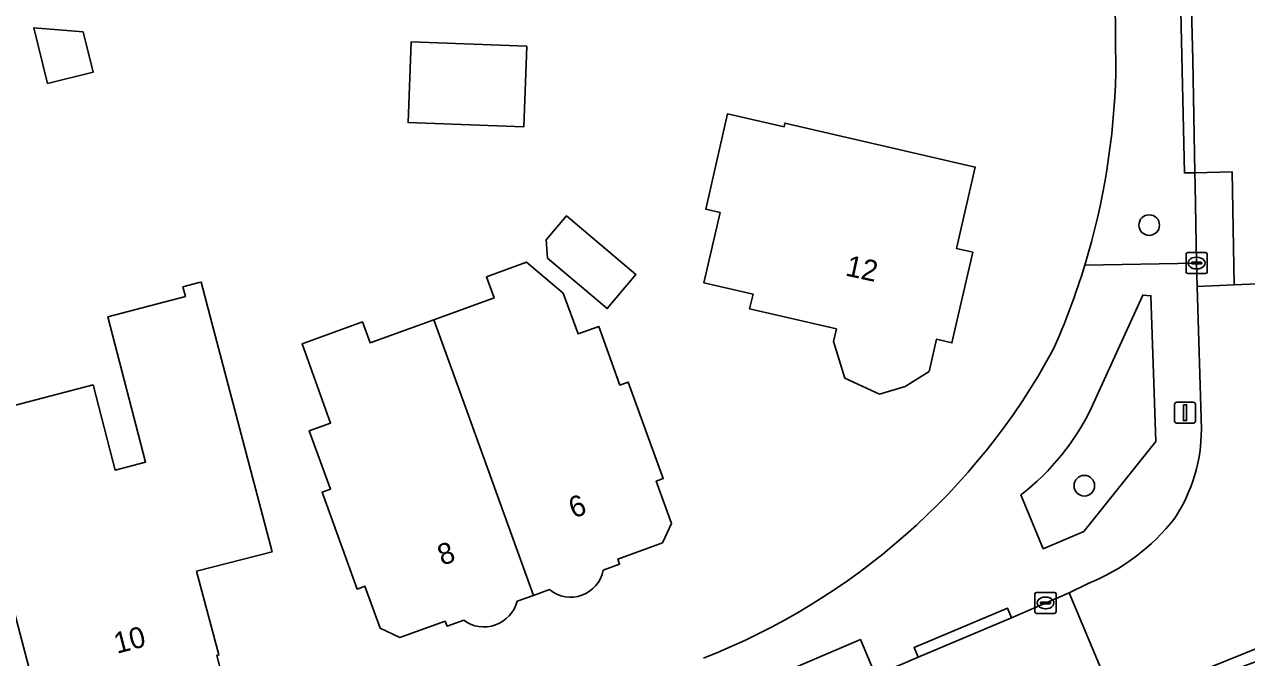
# Model space of a CAD drawing. Extents: x 161772 to 163126, y 383092 to 383917.
# Drawn here: x 162222.7 to 162280.8, y 383514.6 to 383544.7 of the extents above; entities that cross this region are included whole.
import ezdxf

# ---------------------------------------------------------------- set-up
doc = ezdxf.new("R2010")
doc.units = 0
for name, color, linetype in [('IMGEO_Boom', 7, 'Continuous'), ('IMGEO_Erf', 7, 'Continuous'), ('IMGEO_Groenvoorziening', 7, 'Continuous'), ('IMGEO_Kolk', 7, 'Continuous'), ('IMGEO_Lichtmast', 7, 'Continuous'), ('IMGEO_Pand', 7, 'Continuous'), ('IMGEO_Pand_nummerreeks', 7, 'Continuous'), ('IMGEO_Parkeervlak_open', 7, 'Continuous'), ('IMGEO_Rijbaan_lokaal_gesloten', 7, 'Continuous'), ('IMGEO_Rijbaan_lokaal_open', 7, 'Continuous'), ('IMGEO_Voetpad_gesloten', 7, 'Continuous'), ('IMGEO_Voetpad_open', 7, 'Continuous')]:
    doc.layers.add(name, color=color, linetype=linetype)

msp = doc.modelspace()

# ---------------------------------------------------------------- linework, layer by layer
at = {"layer": 'IMGEO_Boom'}
for centre in [(162276.194, 383535.151), (162273.111, 383522.755)]:
    msp.add_circle(centre, 0.489, dxfattribs=at)
at = {"layer": 'IMGEO_Erf'}
for points in [[(162274.609, 383542.395), (162274.444, 383559.797)], [(162243.597, 383516.356), (162242.809, 383516.07), (162242.72, 383516.314), (162240.566, 383515.536), (162239.621, 383515.979), (162238.9, 383517.975), (162238.533, 383517.842), (162236.868, 383522.449), (162237.26, 383522.591), (162236.256, 383525.371), (162237.271, 383525.737), (162235.911, 383529.502), (162238.792, 383530.543), (162239.149, 383529.555), (162242.185, 383530.652), (162245.042, 383531.684), (162244.678, 383532.692), (162246.59, 383533.384)], [(162246.59, 383533.384), (162248.335, 383531.912), (162249.034, 383529.977), (162250.017, 383530.332), (162251.025, 383527.543), (162251.426, 383527.688), (162253.084, 383523.098), (162252.751, 383522.977), (162253.481, 383520.957), (162253.049, 383520.038), (162250.922, 383519.269), (162251.012, 383519.019), (162250.231, 383518.737)], [(162247.685, 383517.82), (162246.912, 383517.541), (162246.142, 383517.263)]]:
    msp.add_lwpolyline(points, dxfattribs=at)
for points in [[(162223.812, 383541.883), (162223.151, 383544.53), (162225.5, 383544.334), (162225.977, 383542.423)], [(162246.598, 383543.656), (162246.456, 383539.819), (162240.956, 383540.022), (162241.098, 383543.859)], [(162255.788, 383535.749), (162255.104, 383535.907), (162256.15, 383540.446), (162258.83, 383539.829), (162258.869, 383539.999), (162263.049, 383539.035), (162267.921, 383537.912), (162267.028, 383534.038), (162267.806, 383533.859), (162266.813, 383529.551), (162266.079, 383529.721), (162265.727, 383528.193), (162264.591, 383527.482), (162263.362, 383527.107), (162261.717, 383527.865), (162261.181, 383529.615), (162261.319, 383530.213), (162257.194, 383531.164), (162257.358, 383531.873), (162255.019, 383532.412)], [(162247.576, 383533.58), (162247.527, 383534.45), (162248.479, 383535.587), (162251.787, 383532.795), (162250.422, 383531.178)], [(162231.022, 383532.419), (162231.115, 383532.443), (162231.625, 383530.499), (162234.483, 383519.611), (162230.896, 383518.695), (162231.959, 383514.707), (162231.853, 383514.679), (162232.162, 383513.494), (162231.579, 383513.336), (162231.816, 383512.378), (162228.506, 383511.506), (162228.256, 383512.479), (162224.639, 383511.519), (162223.972, 383514.088), (162222.998, 383513.832), (162221.834, 383518.302), (162219.838, 383525.954), (162225.972, 383527.553), (162227.031, 383523.493), (162228.474, 383523.869), (162226.67, 383530.788), (162230.368, 383531.753), (162230.247, 383532.217)]]:
    msp.add_lwpolyline(points, close=True, dxfattribs=at)
for centre, radius, start, end in [((162240.224, 383543.256), 34.395, 343.07499, 358.56529), ((162240.409, 383543.176), 34.195, 335.87658, 343.11386), ((162243.211, 383544.682), 32.352, 291.38148, 331.40902), ((162248.692, 383519.017), 1.564, 229.91075, 349.70454), ((162244.56, 383517.677), 1.635, 233.90731, 345.32331)]:
    msp.add_arc(centre, radius, start, end, dxfattribs=at)
at = {"layer": 'IMGEO_Groenvoorziening'}
for points in [[(162276.505, 383524.852), (162276.276, 383531.794), (162275.891, 383531.818), (162273.473, 383526.507)], [(162270.086, 383522.316), (162271.153, 383519.757), (162273.085, 383520.577), (162276.505, 383524.852)]]:
    msp.add_lwpolyline(points, dxfattribs=at)
msp.add_lwpolyline([(162258.144, 383511.658), (162263.172, 383513.747), (162262.46, 383515.448), (162257.425, 383513.279)], close=True, dxfattribs=at)
msp.add_arc((162263.026, 383531.485), 11.572, 307.5929, 334.51957, dxfattribs=at)
at = {"layer": 'IMGEO_Kolk'}
for p, q in [((162278.024, 383533.844), (162278.876, 383533.844)), ((162277.949, 383532.918), (162277.949, 383533.77)), ((162278.208, 383533.338), (162278.208, 383533.35)), ((162278.646, 383533.301), (162278.248, 383533.301)), ((162278.251, 383533.387), (162278.649, 383533.387)), ((162278.437, 383533.624), (162278.462, 383533.624)), ((162278.692, 383533.35), (162278.692, 383533.338)), ((162278.95, 383533.77), (162278.95, 383532.918)), ((162278.876, 383532.844), (162278.024, 383532.844)), ((162278.46, 383533.064), (162278.435, 383533.064)), ((162270.763, 383516.756), (162270.763, 383517.608)), ((162270.838, 383517.682), (162271.69, 383517.682)), ((162271.764, 383517.608), (162271.764, 383516.756)), ((162271.022, 383517.176), (162271.022, 383517.188)), ((162271.46, 383517.139), (162271.062, 383517.139)), ((162271.065, 383517.225), (162271.463, 383517.225)), ((162271.251, 383517.462), (162271.276, 383517.462)), ((162271.506, 383517.188), (162271.506, 383517.176)), ((162271.69, 383516.682), (162270.838, 383516.682)), ((162271.274, 383516.902), (162271.249, 383516.902))]:
    msp.add_line(p, q, dxfattribs=at)
for points in [[(162278.024, 383533.844), (162278.876, 383533.844)], [(162277.949, 383532.918), (162277.949, 383533.77)], [(162278.95, 383533.77), (162278.95, 383532.918)], [(162278.876, 383532.844), (162278.024, 383532.844)], [(162270.763, 383516.756), (162270.763, 383517.608)], [(162270.838, 383517.682), (162271.69, 383517.682)], [(162271.764, 383517.608), (162271.764, 383516.756)], [(162271.69, 383516.682), (162270.838, 383516.682)]]:
    msp.add_lwpolyline(points, dxfattribs=at)
for centre, radius, start, end in [((162278.026, 383533.768), 0.0765, 91.55205, 178.44795), ((162278.026, 383533.768), 0.0765, 91.55205, 178.44795), ((162278.874, 383533.768), 0.0765, 1.55205, 88.44795), ((162278.874, 383533.768), 0.0765, 1.55205, 88.44795), ((162278.248, 383533.347), 0.0403, 85.87752, 175.75265), ((162278.245, 383533.337), 0.0366, 178.93798, 274.71019), ((162278.649, 383533.344), 0.043, 264.86636, 352.45326), ((162278.653, 383533.349), 0.0386, 1.73085, 96.63898), ((162278.026, 383532.92), 0.0765, 181.55205, 268.44795), ((162278.026, 383532.92), 0.0765, 181.55205, 268.44795), ((162278.874, 383532.92), 0.0765, 271.55205, 358.44795), ((162278.874, 383532.92), 0.0765, 271.55205, 358.44795), ((162270.84, 383517.606), 0.0765, 91.55205, 178.44795), ((162270.84, 383517.606), 0.0765, 91.55205, 178.44795), ((162271.688, 383517.606), 0.0765, 1.55205, 88.44795), ((162271.688, 383517.606), 0.0765, 1.55205, 88.44795), ((162271.062, 383517.185), 0.0403, 85.87752, 175.75265), ((162271.059, 383517.175), 0.0366, 178.93798, 274.71019), ((162271.463, 383517.182), 0.043, 264.86636, 352.45326), ((162271.467, 383517.187), 0.0386, 1.73085, 96.63898), ((162270.84, 383516.758), 0.0765, 181.55205, 268.44795), ((162270.84, 383516.758), 0.0765, 181.55205, 268.44795), ((162271.688, 383516.758), 0.0765, 271.55205, 358.44795), ((162271.688, 383516.758), 0.0765, 271.55205, 358.44795)]:
    msp.add_arc(centre, radius, start, end, dxfattribs=at)
for centre, major_axis, ratio, start_param, end_param in [((162278.436, 383533.344), (-0.387, 0.002), 0.722429, 4.712389, 7.853982), ((162278.461, 383533.344), (-0.39, 0.002), 0.717154, 1.570796, 4.712389), ((162271.25, 383517.182), (-0.387, 0.002), 0.722429, 4.712389, 7.853982), ((162271.275, 383517.182), (-0.39, 0.002), 0.717154, 1.570796, 4.712389)]:
    msp.add_ellipse(centre, major_axis=major_axis, ratio=ratio, start_param=start_param, end_param=end_param, dxfattribs=at)
at = {"layer": 'IMGEO_Lichtmast'}
for p, q in [((162277.402, 383525.829), (162277.402, 383526.629)), ((162277.402, 383526.629), (162277.402, 383525.829)), ((162277.502, 383526.729), (162278.292, 383526.729)), ((162278.292, 383526.729), (162277.502, 383526.729)), ((162278.392, 383526.629), (162278.392, 383525.829)), ((162278.392, 383525.829), (162278.392, 383526.629)), ((162278.292, 383525.729), (162277.502, 383525.729)), ((162277.502, 383525.729), (162278.292, 383525.729))]:
    msp.add_line(p, q, dxfattribs=at)
msp.add_lwpolyline([(162277.822, 383526.604), (162277.972, 383526.604), (162277.972, 383525.854), (162277.822, 383525.854), (162277.822, 383526.604)], dxfattribs=at)
for centre, start, end in [((162277.502, 383526.629), 90, 180), ((162277.502, 383526.629), 90, 180), ((162278.292, 383526.629), 0, 90), ((162278.292, 383526.629), 360, 90), ((162277.502, 383525.829), 180, 270), ((162277.502, 383525.829), 180, 270), ((162278.292, 383525.829), 270, 0), ((162278.292, 383525.829), 270, 0)]:
    msp.add_arc(centre, 0.1, start, end, dxfattribs=at)
at = {"layer": 'IMGEO_Pand'}
for points in [[(162223.812, 383541.883), (162225.977, 383542.423), (162225.5, 383544.334), (162223.151, 383544.53)], [(162246.598, 383543.656), (162241.098, 383543.859), (162240.956, 383540.022), (162246.456, 383539.819)], [(162257.358, 383531.873), (162257.194, 383531.164), (162261.319, 383530.213), (162261.181, 383529.615), (162261.717, 383527.865), (162263.362, 383527.107), (162264.591, 383527.482), (162265.727, 383528.193), (162266.079, 383529.721), (162266.813, 383529.551), (162267.806, 383533.859), (162267.028, 383534.038), (162267.921, 383537.912), (162263.049, 383539.035), (162258.869, 383539.999), (162258.83, 383539.829), (162256.15, 383540.446), (162255.104, 383535.907), (162255.788, 383535.749), (162255.019, 383532.412)], [(162248.479, 383535.587), (162247.527, 383534.45), (162247.576, 383533.58), (162250.422, 383531.178), (162251.787, 383532.795)], [(162231.625, 383530.499), (162231.115, 383532.443), (162231.022, 383532.419), (162230.247, 383532.217), (162230.368, 383531.753), (162226.67, 383530.788), (162228.474, 383523.869), (162227.031, 383523.493), (162225.972, 383527.553), (162219.838, 383525.954), (162221.834, 383518.302), (162222.998, 383513.832), (162223.972, 383514.088), (162224.639, 383511.519), (162228.256, 383512.479), (162228.506, 383511.506), (162231.816, 383512.378), (162231.579, 383513.336), (162232.162, 383513.494), (162231.853, 383514.679), (162231.959, 383514.707), (162230.896, 383518.695), (162234.483, 383519.611)]]:
    msp.add_lwpolyline(points, close=True, dxfattribs=at)
for points in [[(162250.231, 383518.737), (162251.012, 383519.019), (162250.922, 383519.269), (162253.049, 383520.038), (162253.481, 383520.957), (162252.751, 383522.977), (162253.084, 383523.098), (162251.426, 383527.688), (162251.025, 383527.543), (162250.017, 383530.332), (162249.034, 383529.977), (162248.335, 383531.912), (162246.59, 383533.384), (162244.678, 383532.692), (162245.042, 383531.684), (162242.185, 383530.652), (162243.54, 383526.893), (162246.912, 383517.541), (162247.685, 383517.82)], [(162246.142, 383517.263), (162246.912, 383517.541), (162243.54, 383526.893), (162242.185, 383530.652), (162239.149, 383529.555), (162238.792, 383530.543), (162235.911, 383529.502), (162237.271, 383525.737), (162236.256, 383525.371), (162237.26, 383522.591), (162236.868, 383522.449), (162238.533, 383517.842), (162238.9, 383517.975), (162239.621, 383515.979), (162240.566, 383515.536), (162242.72, 383516.314), (162242.809, 383516.07), (162243.597, 383516.356)]]:
    msp.add_lwpolyline(points, dxfattribs=at)
for centre, radius, start, end in [((162248.692, 383519.017), 1.564, 229.91075, 349.70454), ((162244.56, 383517.677), 1.635, 233.90731, 345.32331)]:
    msp.add_arc(centre, radius, start, end, dxfattribs=at)
at = {"layer": 'IMGEO_Parkeervlak_open'}
msp.add_lwpolyline([(162280.132, 383537.677), (162278.369, 383537.642), (162278.386, 383537.045), (162278.451, 383533.344), (162278.481, 383532.232), (162280.234, 383532.311)], close=True, dxfattribs=at)
at = {"layer": 'IMGEO_Rijbaan_lokaal_gesloten'}
msp.add_lwpolyline([(162232.719, 383498.477), (162232.788, 383498.498), (162232.857, 383498.517), (162240.887, 383500.821), (162243.486, 383501.569), (162252.383, 383504.531), (162257.966, 383506.692), (162263.678, 383509.123), (162274.11, 383513.54), (162272.382, 383517.659), (162269.646, 383516.479), (162265.21, 383514.61), (162264.518, 383514.306), (162263.172, 383513.747), (162258.144, 383511.658), (162256.707, 383511.061), (162255.312, 383510.481)], dxfattribs=at)
at = {"layer": 'IMGEO_Rijbaan_lokaal_open'}
for points in [[(162278.129, 383548.282), (162278.172, 383546.716), (162278.208, 383545.419), (162278.262, 383543.027), (162278.369, 383537.642), (162280.132, 383537.677), (162280.234, 383532.311), (162283.53, 383532.459), (162283.187, 383549.72)], [(162285.569, 383530.634), (162285.455, 383532.546), (162283.53, 383532.459), (162280.234, 383532.311), (162278.481, 383532.232), (162278.676, 383525.441)], [(162273.292, 383518.111), (162272.382, 383517.659), (162274.11, 383513.54), (162274.699, 383512.137), (162279.146, 383514.141), (162282.946, 383515.674), (162285.57, 383516.52), (162286.631, 383516.849)]]:
    msp.add_lwpolyline(points, dxfattribs=at)
for centre, radius, start, end in [((162270.945, 383525.442), 7.731, 326.77271, 359.99023), ((162269.534, 383527.403), 10.023, 292.01944, 321.80931)]:
    msp.add_arc(centre, radius, start, end, dxfattribs=at)
at = {"layer": 'IMGEO_Voetpad_gesloten'}
for points in [[(162278.481, 383532.232), (162278.451, 383533.344), (162273.13, 383533.243)], [(162278.676, 383525.441), (162278.481, 383532.232)], [(162275.891, 383531.818), (162276.276, 383531.794), (162276.505, 383524.852), (162273.085, 383520.577), (162271.153, 383519.757), (162270.086, 383522.316)], [(162273.473, 383526.507), (162275.891, 383531.818)], [(162256.015, 383512.721), (162256.707, 383511.061), (162258.144, 383511.658), (162257.425, 383513.279), (162262.46, 383515.448), (162263.172, 383513.747), (162264.518, 383514.306), (162265.21, 383514.61), (162265.016, 383515.069), (162269.452, 383516.939), (162269.646, 383516.479), (162272.382, 383517.659), (162273.292, 383518.111)]]:
    msp.add_lwpolyline(points, dxfattribs=at)
for centre, radius, start, end in [((162240.409, 383543.176), 34.195, 335.87658, 343.11386), ((162243.211, 383544.682), 32.352, 291.38148, 331.40902), ((162263.026, 383531.485), 11.572, 307.5929, 334.51957), ((162270.945, 383525.442), 7.731, 326.77271, 359.99023), ((162269.534, 383527.403), 10.023, 292.01944, 321.80931)]:
    msp.add_arc(centre, radius, start, end, dxfattribs=at)
at = {"layer": 'IMGEO_Voetpad_open'}
for points in [[(162273.743, 383601.16), (162274.444, 383559.797), (162274.609, 383542.395)], [(162273.13, 383533.243), (162278.451, 383533.344), (162278.386, 383537.045), (162278.369, 383537.642), (162277.87, 383537.632), (162277.674, 383546.706), (162278.172, 383546.716), (162278.129, 383548.282)]]:
    msp.add_lwpolyline(points, dxfattribs=at)
for points in [[(162278.369, 383537.642), (162278.262, 383543.027), (162278.208, 383545.419), (162278.172, 383546.716), (162277.674, 383546.706), (162277.87, 383537.632)], [(162265.21, 383514.61), (162269.646, 383516.479), (162269.452, 383516.939), (162265.016, 383515.069)], [(162279.146, 383514.141), (162279.319, 383513.673), (162285.743, 383516.052), (162285.57, 383516.52), (162282.946, 383515.674)]]:
    msp.add_lwpolyline(points, close=True, dxfattribs=at)
msp.add_arc((162240.224, 383543.256), 34.395, 343.07499, 358.56529, dxfattribs=at)

# ---------------------------------------------------------------- texts
at = {"layer": 'IMGEO_Pand_nummerreeks'}
for s, rotation, p in [('12', 347.68757, (162261.709, 383532.758)), ('6', 19.83186, (162248.814, 383521.19)), ('8', 19.83186, (162242.576, 383518.941)), ('10', 14.49583, (162227.11, 383514.76))]:
    msp.add_text(s, height=1, rotation=rotation, dxfattribs=at).set_placement(p)

doc.saveas('drawing.dxf')
